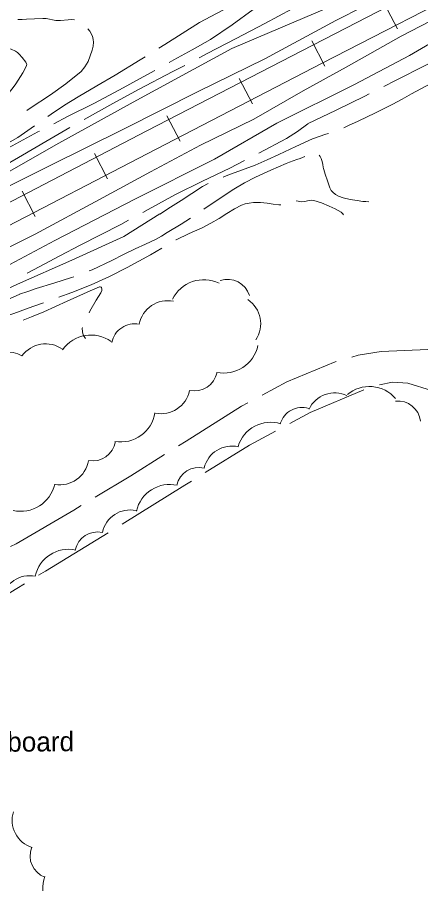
# Model space of a CAD drawing. Extents: x 2361284 to 2366480, y 6976556 to 6985346.
# Drawn here: x 2364182.3 to 2364281.2, y 6978509.3 to 6978721.9 of the extents above; entities that cross this region are included whole.
import ezdxf

# ---------------------------------------------------------------- set-up
doc = ezdxf.new("R2010")
doc.units = 0
doc.header["$LTSCALE"] = 1.9
for name, color, linetype, lineweight in [('11', 7, 'Continuous', 13), ('12', 7, 'Continuous', 13), ('13', 7, 'Continuous', 13), ('15', 7, 'Continuous', 13), ('16', 7, 'Continuous', 13), ('20', 7, 'Continuous', 13), ('22', 7, 'Continuous', 13), ('29', 7, 'Continuous', 13)]:
    doc.layers.add(name, color=color, linetype=linetype, lineweight=lineweight)

msp = doc.modelspace()

# ---------------------------------------------------------------- linework, layer by layer
at = {"layer": '12'}
msp.add_lwpolyline([(2364083.777, 6978605.938), (2364089.996, 6978609.258), (2364102.074, 6978615.943), (2364118.289, 6978623.778), (2364132.662, 6978630.886), (2364142.678, 6978635.59), (2364151.802, 6978640.557), (2364160.135, 6978645.426), (2364170.933, 6978651.06), (2364182.343, 6978656.449), (2364195.668, 6978662.296), (2364208.403, 6978668.106), (2364217.26, 6978673.692)], dxfattribs=at)
at = {"layer": '13'}
for points in [[(2364316.907, 6978749.303), (2364313.473, 6978747.58), (2364304.173, 6978743.362), (2364291.676, 6978737.742), (2364273.995, 6978728.114), (2364260.412, 6978721.104), (2364242.99, 6978711.738), (2364226.685, 6978703.713), (2364208.352, 6978694.457), (2364190.207, 6978685.475), (2364168.479, 6978674.628), (2364150.769, 6978665.128), (2364132.758, 6978655.598), (2364116.035, 6978647.397), (2364101.248, 6978639.726), (2364087.697, 6978633.368), (2364076.324, 6978627.239), (2364064.329, 6978621.474), (2364055.005, 6978617.546), (2364048.402, 6978614.643), (2364040.227, 6978611.065), (2364032.027, 6978606.637)], [(2364320.846, 6978741.031), (2364317.59, 6978739.54), (2364310.146, 6978735.718), (2364301.969, 6978731.13), (2364295.123, 6978727.505), (2364285.873, 6978722.206), (2364276.399, 6978717.277), (2364262.941, 6978709.688), (2364252.425, 6978703.897), (2364240.292, 6978696.902), (2364227.251, 6978690.538), (2364214.992, 6978683.981), (2364202.477, 6978677.171), (2364186.695, 6978668.74), (2364170.8, 6978660.879), (2364156.681, 6978653.385), (2364138.204, 6978643.408), (2364121.923, 6978633.953), (2364110.521, 6978627.734), (2364094.521, 6978619.291), (2364075.604, 6978609.261), (2364063.636, 6978602.807), (2364048.497, 6978595.203), (2364040.513, 6978590.407)], [(2364271.539, 6978729.88), (2364252.804, 6978721.862), (2364234.916, 6978714.261), (2364211.606, 6978701.559), (2364192.514, 6978691.066), (2364173.944, 6978680.48), (2364159.698, 6978673.554), (2364139.756, 6978664.253), (2364125.053, 6978657.144), (2364118.707, 6978653.514), (2364104.067, 6978646.083), (2364092.095, 6978639.919), (2364081.369, 6978634.147), (2364067.98, 6978626.579), (2364056.145, 6978619.746), (2364051.183, 6978617.739), (2364044.277, 6978615.273), (2364038.087, 6978612.114), (2364031.238, 6978607.659)], [(2364301.264, 6978725.323), (2364290.21, 6978719.437), (2364278.454, 6978712.585), (2364264.992, 6978705.397), (2364245.94, 6978695.915), (2364230.683, 6978687.12), (2364211.127, 6978677.274), (2364191.552, 6978667.116), (2364174.308, 6978657.983), (2364160.441, 6978650.12), (2364138.84, 6978638.584), (2364124.005, 6978630.643), (2364117.793, 6978627.583), (2364100.712, 6978619.27), (2364088.197, 6978612.321), (2364078.027, 6978606.854), (2364068.178, 6978601.63), (2364061.939, 6978598.331), (2364053.285, 6978594.358)], [(2364085.975, 6978605.119), (2364091.252, 6978607.64), (2364096.11, 6978610.302), (2364102.506, 6978614.002), (2364105.745, 6978615.778), (2364119.886, 6978623.063), (2364131.284, 6978628.642), (2364139.965, 6978632.715), (2364144.887, 6978634.801), (2364149.194, 6978636.885), (2364157.696, 6978641.273), (2364170.57, 6978648.306), (2364174.622, 6978650.313), (2364182.896, 6978653.974)]]:
    msp.add_lwpolyline(points, dxfattribs=at)
at = {"layer": '15'}
for points in [[(2364284.201, 6978640.356), (2364282.91, 6978640.433), (2364271.524, 6978639.905), (2364265.853, 6978638.991), (2364264.347, 6978638.557)], [(2364260.508, 6978637.44), (2364260.249, 6978637.368), (2364248.394, 6978632.446), (2364242.315, 6978629.188)], [(2364271.081, 6978631.752), (2364274.246, 6978632.382), (2364278.049, 6978632.128), (2364283.807, 6978630.323), (2364289.339, 6978626.984), (2364289.692, 6978626.677)], [(2364249.091, 6978622.281), (2364254.075, 6978624.969), (2364267.294, 6978630.526)], [(2364238.793, 6978627.293), (2364237.281, 6978626.479), (2364223.711, 6978617.92), (2364221.812, 6978616.731)], [(2364228.365, 6978610.194), (2364239.232, 6978616.967), (2364245.568, 6978620.378)], [(2364218.422, 6978614.609), (2364210.131, 6978609.42), (2364201.381, 6978604.147)], [(2364207.984, 6978597.509), (2364223.384, 6978607.076), (2364224.975, 6978608.071)], [(2364197.95, 6978602.084), (2364196.131, 6978600.987), (2364182.008, 6978592.752), (2364180.665, 6978592.029)], [(2364187.491, 6978585.014), (2364189.202, 6978586.05), (2364204.574, 6978595.417)], [(2364166.714, 6978573.046), (2364170.827, 6978574.905), (2364184.072, 6978582.94)]]:
    msp.add_lwpolyline(points, dxfattribs=at)
at = {"layer": '16'}
for centre, radius, start, end in [((2364228.031, 6978648.987), 8.546, 64.0131, 154.0131), ((2364233.818, 6978651.913), 5.694, 17.81821, 107.81821), ((2364219.187, 6978645.252), 7.125, 78.84776, 168.84776), ((2364234.849, 6978646.728), 7.125, 326.15441, 56.15441), ((2364211.076, 6978641.025), 5.694, 78.84776, 168.84776), ((2364200.378, 6978635.401), 8.546, 54.53706, 144.53706), ((2364189.242, 6978634.665), 7.125, 54.29489, 144.29489), ((2364232.933, 6978643.163), 8.546, 258.12271, 348.12271), ((2364180.301, 6978634.068), 5.694, 56.68024, 146.68024), ((2364225.711, 6978635.936), 5.694, 258.12271, 348.12271), ((2364217.548, 6978631.765), 7.125, 258.42028, 348.42028), ((2364260.113, 6978622.782), 6.973, 64.37294, 154.37294), ((2364268.637, 6978622.973), 8.364, 40.21303, 130.21303), ((2364275.598, 6978622.202), 5.573, 6.09452, 96.09452), ((2364252.109, 6978620.597), 5.573, 72.98822, 162.98822), ((2364207.63, 6978626.263), 8.546, 260.56757, 350.56757), ((2364244.436, 6978614.186), 8.364, 72.98822, 162.98822), ((2364200.735, 6978618.748), 5.694, 260.31998, 350.31998), ((2364234.912, 6978609.735), 6.973, 76.86208, 166.86208), ((2364192.736, 6978614.315), 7.125, 260.31998, 350.31998), ((2364226.835, 6978605.876), 5.573, 76.86208, 166.86208), ((2364183.152, 6978609.24), 8.546, 257.31447, 347.31447), ((2364219.688, 6978598.93), 8.364, 77.31474, 167.31474), ((2364209.987, 6978594.059), 6.973, 77.86235, 167.86235), ((2364201.979, 6978590.06), 5.573, 77.86235, 167.86235), ((2364194.879, 6978583.019), 8.364, 77.86235, 167.86235), ((2364185.357, 6978577.926), 6.973, 78.85897, 168.85897), ((2364188.013, 6978524.875), 6.973, 162.60493, 252.60493), ((2364191.017, 6978516.143), 5.573, 159.00321, 249.00321), ((2364196.935, 6978508.145), 8.364, 159.67578, 249.67578)]:
    msp.add_arc(centre, radius, start, end, dxfattribs=at)
at = {"layer": '20'}
for points in [[(2364238.269, 6978730.844), (2364238.302, 6978730.514), (2364238.232, 6978729.474), (2364237.951, 6978728.481), (2364237.491, 6978727.487), (2364237.067, 6978726.783), (2364236.316, 6978725.835), (2364235.374, 6978725.066), (2364231.154, 6978722.836), (2364226.984, 6978720.646), (2364222.73, 6978717.947), (2364218.465, 6978715.255), (2364217.034, 6978714.361)], [(2364251.623, 6978725.081), (2364249.654, 6978723.972), (2364242.997, 6978720.389), (2364235.933, 6978716.692), (2364228.867, 6978713.004), (2364226.887, 6978711.965)], [(2364182.446, 6978721.343), (2364183.495, 6978721.383), (2364184.535, 6978721.423), (2364186.563, 6978721.542), (2364188.592, 6978721.661), (2364189.383, 6978721.609), (2364191.728, 6978721.111), (2364192.928, 6978721.103), (2364194.747, 6978721.29), (2364195.656, 6978721.339), (2364196.367, 6978721.285)], [(2364199.608, 6978719.126), (2364200.124, 6978718.481), (2364200.725, 6978717.278), (2364200.933, 6978716.438), (2364200.989, 6978715.789), (2364200.909, 6978714.798), (2364200.678, 6978713.846), (2364199.644, 6978711.046), (2364198.907, 6978709.749), (2364197.927, 6978708.63), (2364194.246, 6978705.624), (2364190.441, 6978702.908), (2364185.481, 6978699.631), (2364184.658, 6978699.063)], [(2364297.067, 6978717.674), (2364296.052, 6978717.094), (2364289.306, 6978713.559), (2364282.488, 6978710.154), (2364275.002, 6978706.372), (2364272.136, 6978704.925)], [(2364175.634, 6978698.297), (2364176.916, 6978700.229), (2364179.145, 6978702.431), (2364180.285, 6978703.502), (2364181.314, 6978704.681), (2364181.945, 6978705.587), (2364182.546, 6978706.533), (2364183.68, 6978708.304), (2364184.181, 6978709.189), (2364184.583, 6978710.073), (2364184.631, 6978710.313), (2364184.599, 6978710.533), (2364184.435, 6978710.911), (2364183.524, 6978712.043), (2364182.766, 6978712.906), (2364182.352, 6978713.262), (2364181.869, 6978713.577), (2364180.845, 6978714.067), (2364179.28, 6978714.543), (2364177.689, 6978714.677), (2364174.22, 6978714.494), (2364173.561, 6978714.418)], [(2364213.633, 6978712.259), (2364212.412, 6978711.497), (2364206.336, 6978707.759), (2364201.771, 6978705.066), (2364197.207, 6978702.392), (2364193.886, 6978700.321), (2364190.596, 6978698.189), (2364189.782, 6978697.602)], [(2364223.344, 6978710.111), (2364220.429, 6978708.583), (2364211.991, 6978704.163), (2364204.996, 6978700.386), (2364198.689, 6978696.836)], [(2364268.564, 6978703.131), (2364267.519, 6978702.601), (2364260.511, 6978699.154), (2364253.472, 6978695.767)], [(2364253.512, 6978695.787), (2364250.99, 6978693.872), (2364248.336, 6978692.177), (2364241.55, 6978688.563)], [(2364186.533, 6978695.271), (2364182.441, 6978692.431), (2364177.258, 6978689.562), (2364172.044, 6978686.752), (2364166.524, 6978683.51), (2364162.416, 6978681.091)], [(2364195.218, 6978694.843), (2364190.325, 6978692.016), (2364182.587, 6978687.533), (2364175.187, 6978683.272), (2364170.93, 6978680.912)], [(2364228.07, 6978674.805), (2364230.594, 6978676.529), (2364235.364, 6978679.784), (2364238.01, 6978681.309), (2364240.737, 6978682.685), (2364244.44, 6978684.411), (2364248.184, 6978686.036), (2364249.061, 6978686.385), (2364249.948, 6978686.723), (2364250.795, 6978687.001), (2364251.633, 6978687.279), (2364252.758, 6978687.76)], [(2364256.306, 6978688.124), (2364256.559, 6978687.766), (2364256.784, 6978687.308), (2364257.031, 6978686.541), (2364257.208, 6978685.772), (2364257.304, 6978685.163), (2364257.357, 6978684.854), (2364257.43, 6978684.554), (2364257.615, 6978683.986), (2364257.801, 6978683.428), (2364258.356, 6978681.763), (2364258.932, 6978680.098), (2364259.269, 6978679.431), (2364259.623, 6978678.995), (2364260.288, 6978678.441), (2364261.052, 6978678.028), (2364262.196, 6978677.629), (2364263.91, 6978677.225), (2364265.662, 6978676.952), (2364267.055, 6978676.745), (2364267.755, 6978676.682), (2364268.455, 6978676.679)], [(2364237.988, 6978686.749), (2364234.395, 6978684.925), (2364227.745, 6978681.682), (2364221.126, 6978678.399), (2364214.4, 6978674.755), (2364213.048, 6978674.022)], [(2364250.691, 6978676.89), (2364251.162, 6978676.784), (2364251.543, 6978676.698), (2364251.924, 6978676.652), (2364252.683, 6978676.719), (2364253.841, 6978676.95), (2364254.41, 6978677.015), (2364254.981, 6978676.961), (2364256.908, 6978676.369), (2364258.785, 6978675.577), (2364260.272, 6978674.921), (2364261.689, 6978674.114), (2364261.861, 6978673.976), (2364262.093, 6978673.728), (2364262.296, 6978673.46)], [(2364221.181, 6978667.278), (2364221.291, 6978667.339), (2364224.447, 6978668.829), (2364227.613, 6978670.289), (2364229.713, 6978671.399), (2364231.792, 6978672.56), (2364233.692, 6978673.738), (2364235.59, 6978674.936), (2364237.302, 6978675.802), (2364238.189, 6978676.121), (2364239.117, 6978676.34), (2364240.236, 6978676.46), (2364241.915, 6978676.436), (2364243.597, 6978676.312), (2364245.029, 6978676.096), (2364246.441, 6978675.889), (2364246.88, 6978675.924), (2364246.92, 6978675.934)], [(2364199.922, 6978659.716), (2364200.63, 6978659.993), (2364205.509, 6978662.24), (2364208.355, 6978663.676), (2364211.192, 6978665.123), (2364213.712, 6978666.257), (2364216.21, 6978667.431), (2364217.642, 6978668.234), (2364219.044, 6978669.078), (2364222.445, 6978671.16), (2364224.741, 6978672.593)], [(2364209.535, 6978672.107), (2364207.675, 6978671.1), (2364202.718, 6978668.572), (2364197.762, 6978666.035), (2364192.717, 6978663.377), (2364187.671, 6978660.71), (2364184.727, 6978659.132)], [(2364192.483, 6978653.255), (2364195.643, 6978654.415), (2364200.455, 6978656.311), (2364204.876, 6978658.343), (2364209.215, 6978660.555), (2364212.102, 6978662.072), (2364214.966, 6978663.629), (2364217.731, 6978665.255)], [(2364182.887, 6978653.944), (2364184.92, 6978654.673), (2364186.962, 6978655.373), (2364191.301, 6978656.694), (2364195.628, 6978658.035), (2364196.196, 6978658.261)], [(2364183.767, 6978647.581), (2364185.79, 6978648.38), (2364188.856, 6978649.67), (2364194.543, 6978652.235), (2364200.209, 6978654.829), (2364201.115, 6978655.237), (2364202.031, 6978655.636), (2364202.281, 6978655.719), (2364202.49, 6978655.751), (2364202.64, 6978655.752), (2364202.75, 6978655.733), (2364202.881, 6978655.684), (2364202.962, 6978655.585), (2364203.055, 6978655.226), (2364203.028, 6978654.906), (2364202.804, 6978654.313), (2364201.671, 6978652.523), (2364200.116, 6978649.827), (2364199.89, 6978649.405)], [(2364175.53, 6978647.193), (2364178.481, 6978648.221), (2364181.421, 6978649.259), (2364186.114, 6978650.935), (2364188.725, 6978651.88)], [(2364198.275, 6978645.779), (2364198.246, 6978645.619), (2364198.265, 6978644.739), (2364198.339, 6978644.31), (2364198.442, 6978644.001), (2364198.676, 6978643.553), (2364199, 6978643.116)]]:
    msp.add_lwpolyline(points, dxfattribs=at)
at = {"layer": '22'}
for points in [[(2364243.126, 6978725.85), (2364240.116, 6978723.831), (2364234.951, 6978720.072), (2364229.664, 6978716.502), (2364225.178, 6978713.959), (2364220.671, 6978711.466), (2364219.537, 6978710.835)], [(2364216.046, 6978708.892), (2364214.026, 6978707.763), (2364207.371, 6978704.089), (2364201.032, 6978700.799), (2364194.652, 6978697.558), (2364191.289, 6978695.816)], [(2364262.352, 6978694.831), (2364263.517, 6978695.363), (2364265.847, 6978696.455), (2364270.137, 6978698.476), (2364274.387, 6978700.576), (2364276.665, 6978701.838), (2364278.934, 6978703.14), (2364281.232, 6978704.401), (2364283.561, 6978705.604), (2364284.348, 6978705.941), (2364285.135, 6978706.269), (2364287.395, 6978707.32)], [(2364187.735, 6978693.981), (2364187.377, 6978693.798), (2364180.185, 6978689.9), (2364175.013, 6978686.901), (2364169.851, 6978683.871), (2364163.426, 6978680.1)], [(2364232.775, 6978682.7), (2364233.882, 6978683.15), (2364237.261, 6978684.372), (2364240.619, 6978685.654), (2364243.535, 6978686.952), (2364246.443, 6978688.28), (2364250.555, 6978690.209), (2364254.667, 6978692.127), (2364257.917, 6978693.218), (2364258.605, 6978693.445)], [(2364217.281, 6978673.642), (2364219.865, 6978675.327), (2364222.459, 6978677.001), (2364225.083, 6978678.706), (2364227.717, 6978680.402), (2364229.08, 6978681.165)]]:
    msp.add_lwpolyline(points, dxfattribs=at)
at = {"layer": '29'}
for p, q in [((2364272.272, 6978725.277), (2364275.492, 6978719.058)), ((2364254.509, 6978716.108), (2364257.719, 6978709.888)), ((2364236.736, 6978706.908), (2364239.956, 6978700.689)), ((2364218.982, 6978697.709), (2364222.201, 6978691.489)), ((2364201.219, 6978688.5), (2364204.448, 6978682.28)), ((2364183.466, 6978679.281), (2364186.694, 6978673.071))]:
    msp.add_line(p, q, dxfattribs=at)
for points in [[(2363926.674, 6978544.462), (2363964.107, 6978564.229), (2364001.623, 6978583.856), (2364042.853, 6978605.198), (2364084.062, 6978626.542), (2364128.694, 6978649.718), (2364173.346, 6978672.904), (2364214.057, 6978694.031), (2364254.768, 6978715.12), (2364294.894, 6978735.833), (2364335.019, 6978756.535), (2364356.186, 6978767.468), (2364377.374, 6978778.399), (2364394.91, 6978787.357), (2364412.486, 6978796.234)], [(2363929.006, 6978540.034), (2363966.429, 6978559.8), (2364003.925, 6978579.417), (2364045.145, 6978600.751), (2364086.354, 6978622.094), (2364130.996, 6978645.279), (2364175.648, 6978668.465), (2364216.349, 6978689.584), (2364257.061, 6978710.672), (2364297.185, 6978731.384), (2364337.311, 6978752.087), (2364358.478, 6978763.02), (2364379.656, 6978773.951), (2364397.172, 6978782.897), (2364414.739, 6978791.766)]]:
    msp.add_lwpolyline(points, dxfattribs=at)

# ---------------------------------------------------------------- texts
at = {"layer": '11'}
msp.add_text('Billboard', height=4.799, rotation=0.545, dxfattribs=at).set_placement((2364171.294, 6978541.608))

doc.saveas('drawing.dxf')
